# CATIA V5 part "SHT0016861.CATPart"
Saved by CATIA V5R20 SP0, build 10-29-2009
Part number: SHT0016861
Bounding box of the stored display mesh (mm): x -44.965 to 52.845, y -513 to 0, z 0 to 609.904
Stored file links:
  F:\福田A6\1-数据\6-冻结数据\第九批\设变\扶手支架设变20241021\更改后数据-20241021\SHT0016861 右扶手支架总成\SHT0016861.CATPart
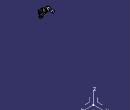
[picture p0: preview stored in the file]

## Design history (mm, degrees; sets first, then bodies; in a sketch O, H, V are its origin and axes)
AxisSystem1: origin (0, 0, 0), X (1, 0, 0), Y (0, 1, 0), Z (0, 0, 1)
Set1
  AxisLine1: Element face of Solid4
  AxisLine2: Element face of Solid4
  Rotate1: ToTransfor AxisLine1, Axis AxisLine2, Angle 90
  Plane1: type 2Lines, Element1 AxisLine2, Element2 Rotate1
  Line1: type PtDir, RefPoint {point type OnCurve, Support edge [face of Solid1 | face of Solid1], Ratio 0}, Direction edge [face of Solid1 | face of Solid1], Start 0, End 3
  Point1: type Center, Curve edge [face of Solid1 | face of Solid1]
  Plane2: type 1Line1Pt, RefPoint Point1, Line Line1
  Plane3: type 1Line1Pt, RefPoint {point type Center, Curve edge [face of Solid2 | face of Solid2]}, Line edge [face of Solid2 | face of Solid2]
Body1 (main body)
Body2 "SHT0011363 轴套"
  Solid1: solid without history
Body3 "SHT0011363 轴套"
  Solid2 "实体.1": solid without history
Body4 "焊道"
  Solid3 "实体.1": solid without history
Body5 "SHT0013120 扶手转轴"
  Solid4 "实体.3": solid without history
  Rotate2: ToTransfor Solid4, Angle -5, Axis axis of face of Solid4
Body6 "SHT0014367 H6扶手支架"
  Solid5 "实体.4": solid without history
Body7 "焊道"
  Sketch1 on Plane2, origin (-198.5947, -0.0001, 489.1834), H (0, -1, 0), V (0.9266, 0, 0.3762)
    line L1 (506.0002, 244.7868) -> (503.0002, 241.7868)
    point P1 (506.0002, 244.7868)
    point P2 (503.0002, 241.7868)
    projected line E1 (503.0002, 244.7868) -> (506.0002, 244.7868) from Line1
    point P4 (506.0002, 244.7868)
    line L2 (503.0002, 244.7868) -> (503.0002, 241.7868)
    point P5 (503.0002, 241.7868)
    angle L1 L2 = 45
    coincidence: P1 P4, P2 P5
    vertical: L2 V
  Rib1: profile Sketch1, centre curve edge [face of Solid1 | face of Solid1]
  Rib2: profile Sketch1, centre curve edge [face of Solid1 | face of Solid1]
  Sketch2 on face of Solid5, origin (-0.0001, -503.0002, 0), H (1, 0, 0), V (0, 0, 1)
    line L1 (12.8351, 568.0498) -> (31.0526, 580.5964)
    line L2 (23.4601, 605.3796) -> (32.9712, 591.5697)
    reference projected point E2 (37.4799, 585.023) from Point1
    line L3 (12.8351, 568.0498) -> (65.2636, 544.6814)
    line L4 (23.4601, 605.3796) -> (66.9423, 605.3141)
    line L5 (32.9712, 591.5697) -> (44.5519, 589.8935)
    line L6 (31.0526, 580.5964) -> (41.5777, 579.0731)
    line L7 (44.5519, 589.8935) -> (66.9423, 605.3141)
    line L8 (41.5777, 579.0731) -> (65.2636, 544.6814)
    reference projected line E3 (16.3973, 575.811) -> (21.5423, 603.722) from edge [face of Solid5 | face of Solid5]
    angle L1 E3 = 45
    perpendicularity: L2 L1
    coincidence: L2 E2, L2 L8
    parallelism: L6 L5
    fix: L1
  Pocket1: profile Sketch2, direction (0, -1, 0), length 20
Body8 "焊道"
  Sketch3 on Plane3, origin (188.936, -0.0001, 465.401), H (0, -1, 0), V (-0.9266, 0, 0.3761)
    line L1 (503.0002, 164.2213) -> (503.0002, 161.2213)
    line L2 (506.0002, 164.2213) -> (503.0002, 164.2213)
    construction line L3 (506.0002, 164.2213) -> (506.0002, 157.0498)
    construction line L4 (503.0002, 164.2213) -> (506.0002, 164.2213)
    construction line L5 (503.0002, 157.0498) -> (506.0002, 157.0498)
    point P5 (506.0002, 164.2213)
    line L6 (506.0002, 164.2213) -> (503.0002, 161.2213)
    distance L1 L3 = 3
    angle L6 L1 = 45
    vertical: L1 V
    fix: L2, L1
    perpendicularity: L4 L1, L4 L3, L5 L1, L5 L3
    coincidence: L3 P5
  Rib3: profile Sketch3, centre curve edge [face of Solid2 | face of Solid2]
  Rib4: profile Sketch3, centre curve edge [face of Solid2 | face of Solid2]
  Sketch4 on face of Solid5, origin (-0.0001, -503.0002, 0), H (1, 0, 0), V (0, 0, 1)
    line L1 (60.449, 553.6201) -> (34.1442, 535.5037)
    reference projected line E1 (45.0878, 540.7922) -> (42.7526, 528.1244) from edge [face of Solid5 | face of Solid5]
    point P3 (27.5095, 530.9342)
    reference projected arc E2 centre (27.5095, 530.9342) radius 4.5 from (31.679, 529.2416) to (23.34, 532.6269) ccw from edge [face of Solid2 | face of Solid2]
    line L2 (9.9825, 556.3832) -> (23.042, 537.421)
    point P4 (9.9825, 556.3832)
    point P6 (9.9825, 556.3832)
    point P8 (21.1674, 526.5664)
    point P10 (32.1831, 524.1481)
    line L3 (21.1674, 526.5664) -> (-9.4182, 505.5018)
    line L4 (32.1831, 524.1481) -> (53.003, 493.9179)
    line L5 (23.042, 537.421) -> (34.1442, 535.5037)
    line L6 (21.1674, 526.5664) -> (32.1831, 524.1481)
    line L7 (9.9825, 556.3832) -> (60.449, 553.6201)
    line L8 (-9.4182, 505.5018) -> (53.003, 493.9179)
    angle L1 E1 = 45
    angle L2 L1 = 90
    concentricity: E2 P3
    coincidence: L1 P3, L2 P3, P6 L2, P8 L1, P10 L2, L1 L3, L2 L4, P4 P6
  Pocket2: profile Sketch4, direction (0, -1, 0), length 20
